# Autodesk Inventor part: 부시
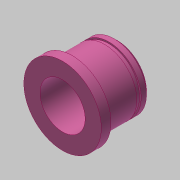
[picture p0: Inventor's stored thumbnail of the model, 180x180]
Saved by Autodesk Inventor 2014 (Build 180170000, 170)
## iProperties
Created: 2019-01
Part Number: 부시
Material: 강철, 연강
Document SubType Name: Modeling
Designer: mduedu
Density: 7.86 g/cm^3
Appearance: 분홍색
Mass: 23.9234 g
Surface Area: 24.4489 cm^2
Volume: 3.04369 cm^3
Author: mduedu
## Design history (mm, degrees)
sketch "스케치1"
  geometry: L1 (0, 0)-(3, 0); L2 (3, 0)-(3, 12); L3 (3, 12)-(0, 12); L4 (0, 12)-(0, 0); L5 (3, 0)-(17, 0); L6 (17, 0)-(17, 10); L7 (17, 10)-(3, 10); L8 (3, 10)-(3, 0)
  constraints: 16 end point, 4 parallel, 2 horizontal, 2 perpendicular
  dimensions: "d0" = 17 distance between parallel lines of L6 L4; "d2" = 3 distance of L2.end L3.end; "d3" = 24 diameter of L3 L1; "d4" = 20 diameter of L7 L5
revolve "회전1" sketch "스케치1" stored, may be unused: angle "d5" = 90 deg
sketch "스케치2"
  geometry: C1 r 7 at (0, 0); 1 further point
  constraints: 1 centre point, 1 coincident
  dimensions: "d6" = 14 diameter of C1
extrude "돌출1" cut sketch "스케치2" stored distance "d7" = 10; taper "d8" = 0 deg
chamfer "모따기1" distance "d9" = 1; stored, may be unused: second distance "d10" = 2, angle "d11" = 45 deg
node "작업 평면1"
sketch "스케치3"
  geometry: C1 r 9.5 at (0, 0); C2 r 10 at (0, 0) reference; 1 further point
  constraints: 1 centre point, 1 coincident
  dimensions: "d13" = 19 diameter of C1
extrude "돌출2" cut sketch "스케치3" distance "d14" = 1.35; taper "d15" = 0 deg
node "솔리드1"
